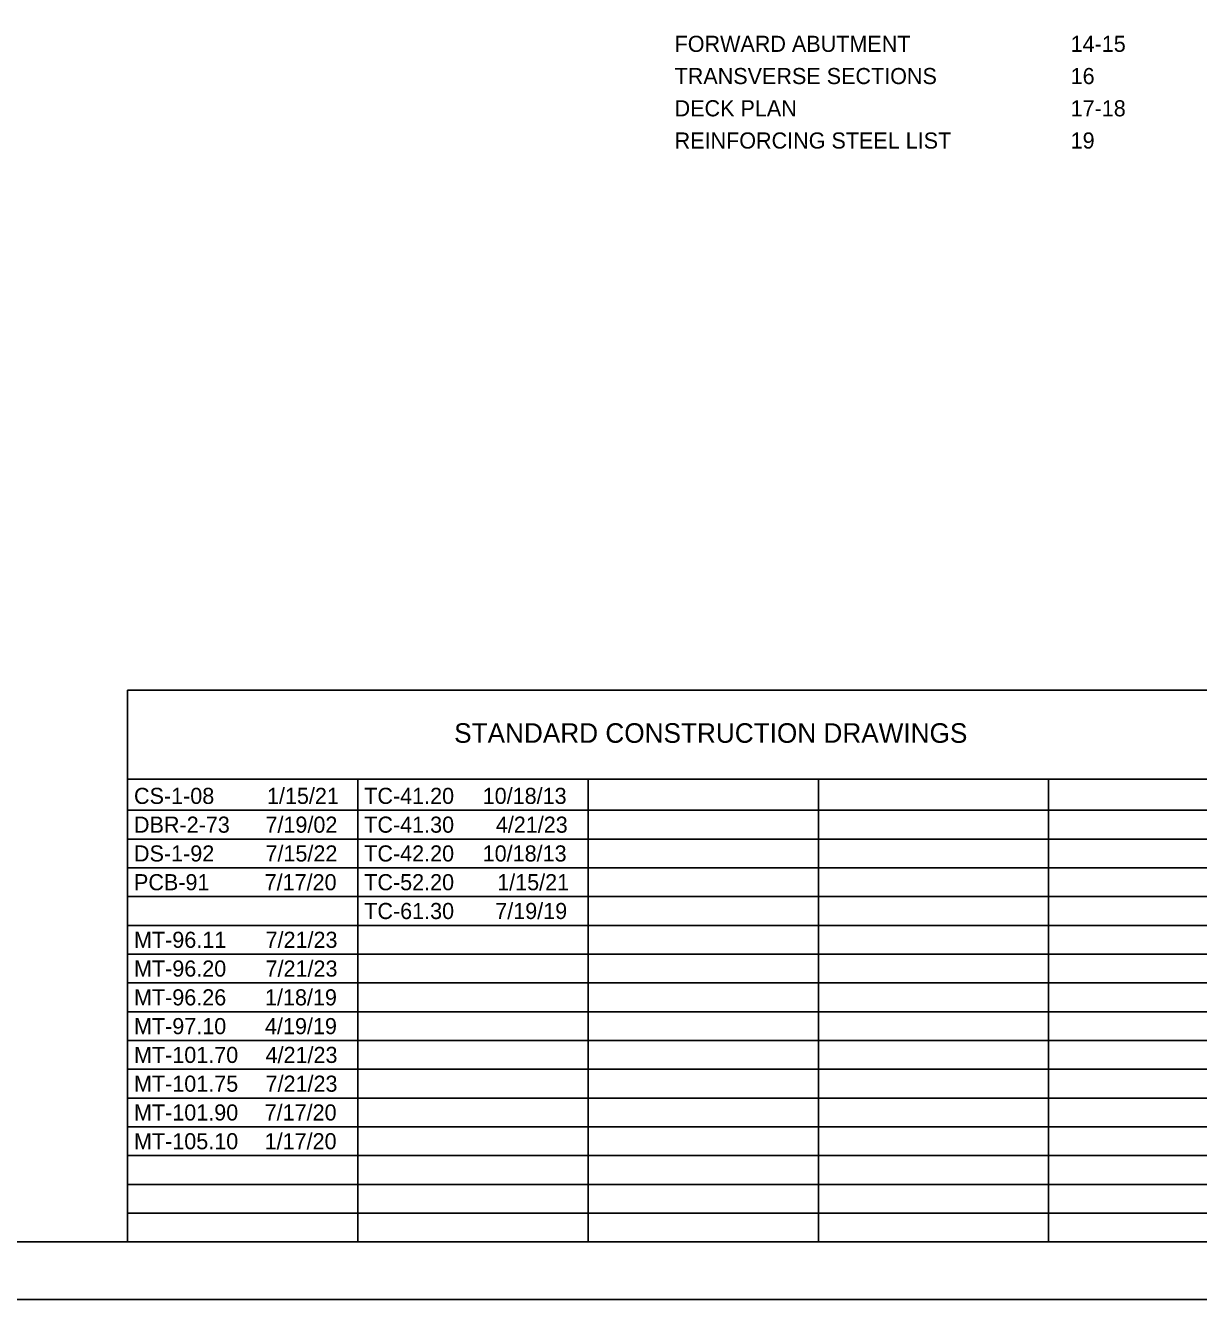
# Model space of a CAD drawing. Extents: x 0 to 34, y 0 to 22.
# Drawn here: x 10.19 to 20.38, y 0 to 11.07 of the extents above; entities that cross this region are included whole.
import ezdxf

# ---------------------------------------------------------------- set-up
doc = ezdxf.new("R2010")
doc.units = 0
for name, color, linetype in [('SH_Border', 7, 'Continuous'), ('SH_Cut_Line', 7, 'Continuous'), ('SH_Data', 7, 'Continuous'), ('SH_Text', 7, 'Continuous')]:
    doc.layers.add(name, color=color, linetype=linetype)

msp = doc.modelspace()

# ---------------------------------------------------------------- linework, layer by layer
at = {"layer": 'SH_Border'}
msp.add_lwpolyline([(1.5, 21.5), (33.5, 21.5), (33.5, 0.5), (1.5, 0.5)], close=True, dxfattribs=at)
at = {"layer": 'SH_Cut_Line'}
msp.add_lwpolyline([(0, 0), (34, 0), (34, 22), (0, 22)], close=True, dxfattribs=at)
at = {"layer": 'SH_Data'}
for p, q in [((11.077, 5.292), (24.527, 5.292)), ((11.077, 0.5), (11.077, 5.292)), ((11.077, 0.5), (11.077, 5.292)), ((11.077, 4.521), (24.527, 4.521)), ((13.077, 0.5), (13.077, 4.521)), ((15.077, 0.5), (15.077, 4.521)), ((17.077, 0.5), (17.077, 4.521)), ((19.077, 0.5), (19.077, 4.521)), ((11.077, 4.25), (24.527, 4.25)), ((11.077, 4), (24.527, 4)), ((11.077, 3.75), (24.527, 3.75)), ((11.077, 3.5), (24.527, 3.5)), ((11.077, 3.25), (24.527, 3.25)), ((11.077, 3), (24.527, 3)), ((11.077, 2.75), (24.527, 2.75)), ((11.077, 2.5), (24.527, 2.5)), ((11.077, 2.25), (24.527, 2.25)), ((11.077, 2), (24.527, 2)), ((11.077, 1.75), (24.527, 1.75)), ((11.077, 1.5), (24.527, 1.5)), ((11.077, 1.25), (24.527, 1.25)), ((11.077, 1), (24.527, 1)), ((11.077, 0.75), (24.527, 0.75))]:
    msp.add_line(p, q, dxfattribs=at)

# ---------------------------------------------------------------- texts
at = {"layer": 'SH_Text'}
for s, height, p in [('FORWARD ABUTMENT', 0.14, (15.828, 10.838)), ('14-15', 0.14, (19.268, 10.838)), ('TRANSVERSE SECTIONS', 0.14, (15.828, 10.558)), ('16', 0.14, (19.268, 10.558)), ('DECK PLAN', 0.14, (15.828, 10.278)), ('17-18', 0.14, (19.268, 10.278)), ('REINFORCING STEEL LIST', 0.14, (15.828, 9.998)), ('19', 0.14, (19.268, 9.998)), ('STANDARD CONSTRUCTION DRAWINGS', 0.17, (13.913, 4.836)), ('CS-1-08  ', 0.14, (11.132, 4.305)), (' 1/15/21', 0.14, (12.235, 4.305)), ('TC-41.20 ', 0.14, (13.132, 4.305)), ('10/18/13', 0.14, (14.161, 4.305)), ('DBR-2-73 ', 0.14, (11.132, 4.055)), (' 7/19/02', 0.14, (12.222, 4.055)), ('TC-41.30 ', 0.14, (13.132, 4.055)), (' 4/21/23', 0.14, (14.223, 4.055)), ('DS-1-92  ', 0.14, (11.132, 3.805)), (' 7/15/22', 0.14, (12.222, 3.805)), ('TC-42.20 ', 0.14, (13.132, 3.805)), ('10/18/13', 0.14, (14.161, 3.805)), ('PCB-91   ', 0.14, (11.132, 3.555)), (' 7/17/20', 0.14, (12.215, 3.555)), ('TC-52.20 ', 0.14, (13.132, 3.555)), (' 1/15/21', 0.14, (14.235, 3.555)), ('TC-61.30 ', 0.14, (13.132, 3.305)), (' 7/19/19', 0.14, (14.218, 3.305)), ('MT-96.11 ', 0.14, (11.132, 3.055)), (' 7/21/23', 0.14, (12.223, 3.055)), ('MT-96.20 ', 0.14, (11.132, 2.805)), (' 7/21/23', 0.14, (12.223, 2.805)), ('MT-96.26 ', 0.14, (11.132, 2.555)), (' 1/18/19', 0.14, (12.218, 2.555)), ('MT-97.10 ', 0.14, (11.132, 2.305)), (' 4/19/19', 0.14, (12.218, 2.305)), ('MT-101.70', 0.14, (11.132, 2.055)), (' 4/21/23', 0.14, (12.223, 2.055)), ('MT-101.75', 0.14, (11.132, 1.805)), (' 7/21/23', 0.14, (12.223, 1.805)), ('MT-101.90', 0.14, (11.132, 1.555)), (' 7/17/20', 0.14, (12.215, 1.555)), ('MT-105.10', 0.14, (11.132, 1.305)), (' 1/17/20', 0.14, (12.215, 1.305))]:
    msp.add_text(s, height=height, dxfattribs=at).set_placement(p)

doc.saveas('drawing.dxf')
